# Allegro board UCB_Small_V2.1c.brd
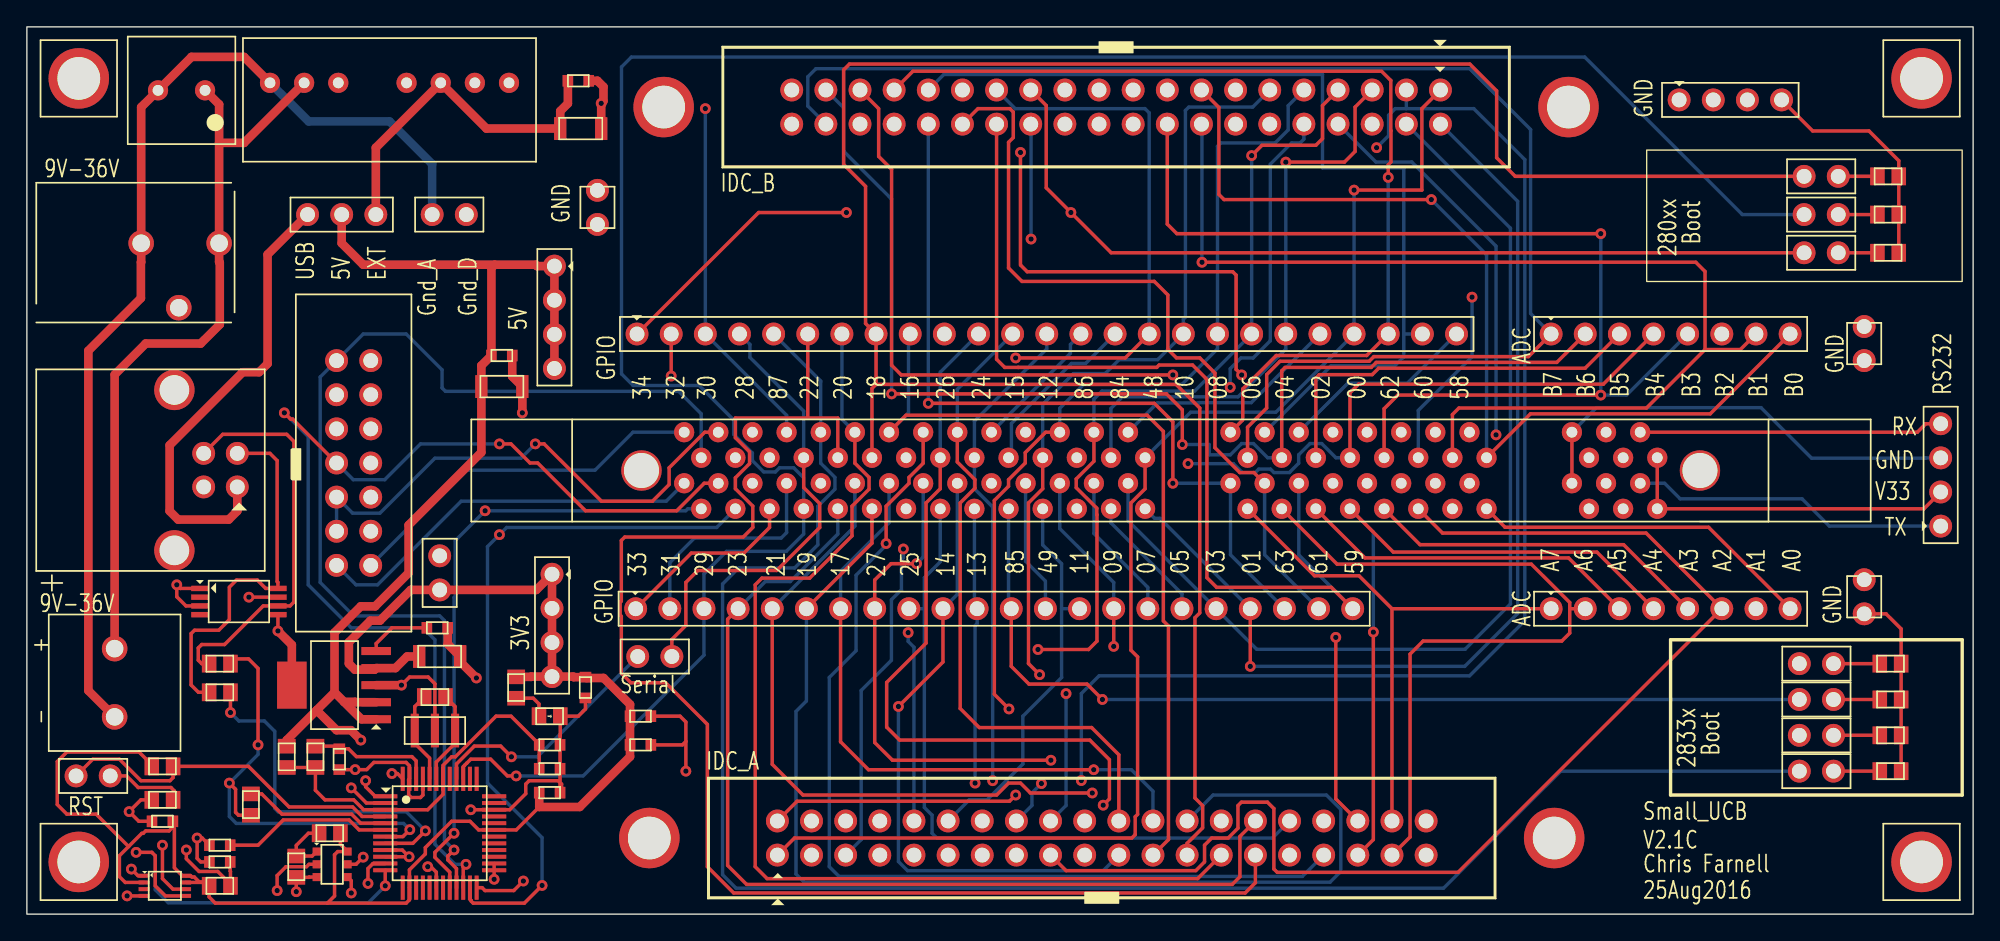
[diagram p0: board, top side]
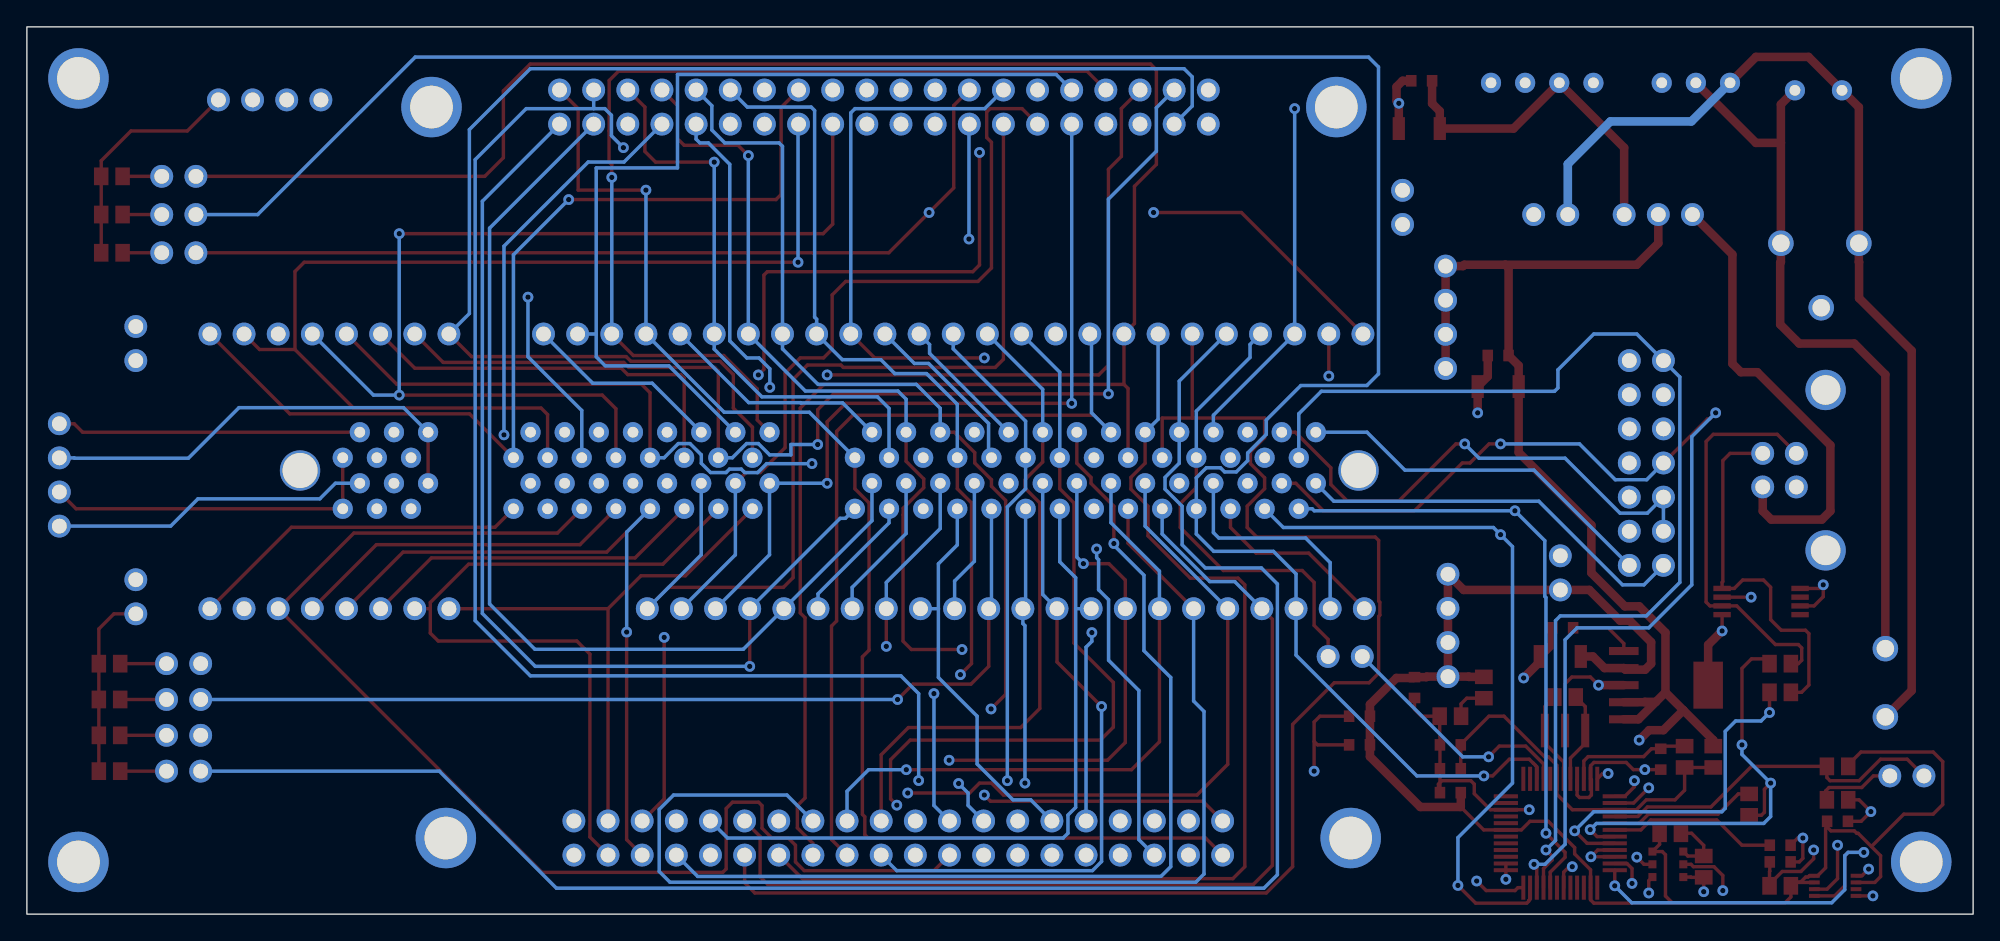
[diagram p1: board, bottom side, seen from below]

Outline 144.78 x 66.04 mm; copper layers: TOP, LAYER2, LAYER3, BOTTOM. Coordinates in mm from the lower left corner of the outline.
Outline path: rectangle 0,0 144.78,66.04

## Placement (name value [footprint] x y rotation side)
C1  100uF  [UVZ1H101MPD]  11.51 61.32 180 top
C2  10uF  [C_1206]  41.2 58.47 0 top
C3  0.1uF  [C_0603]  41.02 62.03 0 top
C4  10uF  [C_1206]  35.33 39.27 0 top
C5  0.1uF  [C_0603]  35.33 41.58 0 top
C6  10uF  [C_1206]  30.71 19.18 0 top
C7  0.1uF  [C_0603]  41.55 16.87 270 top
C8  0.1uF  [C_0603]  30.53 21.31 0 top
C9  0.1uF  [C_0603]  14.35 5.13 0 top
C10  0.1uF  [C_0603]  23.24 11.53 90 top
C11  1uF  [C_0603]  38.89 12.6 0 top
C12  1uF  [C_0603]  38.89 10.82 0 top
C13  0.1uF  [C_0603]  38.89 9.04 0 top
C14  0.1uF  [C_0603]  45.64 14.73 0 top
C15  0.1uF  [C_0603]  45.64 12.6 0 top
C16  0.1uF  [C_0603]  10.08 6.91 180 top
C17  0.1uF  [C_0603]  14.35 3.89 180 top
D1  LED-G  [LED_0805-GREEN]  38.89 14.73 180 top
J1  F28335_DIMM  [5390213-1]  124.46 33.02 180 top
J2  AWHW 14G-0202-T  [14-IDC-M]  24.31 33.58 0 top
J3  Header-4  [H_1X4]  142.37 32.69 180 top
J4  Header_1x22  [H_1X22]  71.96 22.73 90 top
J5  Header_1x25  [H_1X25]  75.87 43.18 90 top
J6  Header_1x8  [H_1X8]  122.28 22.73 90 top
J7  Header_1x8  [H_1X8]  122.28 43.18 90 top
J8  PJ-102BH  [DC-PWR_JACK]  7.95 49.94 90 top
J9  -  [1715721]  6.53 17.22 0 top
J10  670687041  [USB-B_TH]  9.19 33.05 270 top
J11  Header-4  [H_1X4]  39.07 21.49 0 top
J12  Header-4  [H_1X4]  39.24 44.42 0 top
J13  Header-4  [H_1X4]  126.72 60.6 90 top
J14  AWHW 40G-0202-T  [40-IDC-M_MNT]  79.96 5.66 90 top
J15  AWHW 40G-0202-T  [40-IDC-M_MNT]  81.03 60.07 270 top
J16  Header-2  [H_1X2]  136.68 23.62 0 top
J17  Header-2  [H_1X2]  136.68 42.47 0 top
J18  Header-2  [H_1X2]  42.44 52.6 0 top
JP1  -  [J_1X3]  23.42 52.07 90 top
JP2  -  [J_1X2]  31.42 52.07 270 top
JP3  -  [J_1X2]  30.71 25.4 180 top
JP4  -  [J_1X2]  46.71 19.18 90 top
JP5  -  [J_1X2]  4.93 10.29 270 top
JP6  -  [J_1X2]  133.12 10.64 90 top
JP7  -  [J_1X2]  133.12 13.31 90 top
JP8  -  [J_1X2]  133.12 15.98 90 top
JP9  -  [J_1X2]  133.12 18.64 90 top
JP10  -  [J_1X2]  133.48 49.23 90 top
JP11  -  [J_1X2]  133.48 52.07 90 top
JP12  -  [J_1X2]  133.48 54.91 90 top
L1  22uH  [L_0805]  19.33 11.71 270 top
MECH1  Mech_Hole  [4-40_SCREW]  140.94 3.89 0 top
MECH2  Mech_Hole  [4-40_SCREW]  3.86 3.89 0 top
MECH3  Mech_Hole  [4-40_SCREW]  3.86 62.2 0 top
MECH4  Mech_Hole  [4-40_SCREW]  140.94 62.2 0 top
PM1  EC4SAW-24S05N  [SIP-8]  26.97 60.6 90 top
R1  470  [R_0805]  21.46 11.71 90 top
R2  27  [R_0805]  14.35 16.51 0 top
R3  27  [R_0805]  14.35 18.64 0 top
R4  2.2k  [R_0805]  16.66 8.15 90 top
R5  1Meg  [R_0805]  30.35 16.15 180 top
R6  470  [R_0805]  36.4 16.87 270 top
R7  2.2k  [R_0805]  20.04 3.53 270 top
R8  10k  [R_0805]  22.53 6.02 0 top
R9  1k  [R_0805]  14.35 2.11 0 top
R10  47k  [R_0805]  10.08 11 0 top
R11  1k  [R_0805]  10.08 8.51 180 top
R12  2.7k  [R_0805]  138.63 10.64 0 top
R13  2.7k  [R_0805]  138.63 13.31 0 top
R14  2.7k  [R_0805]  138.63 15.98 0 top
R15  2.7k  [R_0805]  138.63 18.64 0 top
R16  2.7k  [R_0805]  138.46 49.23 0 top
R17  2.7k  [R_0805]  138.46 52.07 0 top
R18  2.7k  [R_0805]  138.46 54.91 0 top
TVS1  SN75240PWR  [8-TSSOP]  15.77 23.27 0 top
U1  FT2232D  [LQFP-48]  30.71 6.02 0 top
U2  TPS79533  [SOT-223-6]  22.89 17.04 0 top
U4  SN74LVC2G74  [8-VSSOP]  10.26 2.11 0 top
U5  6 MHz  [CSTCR]  30.35 13.67 90 top
U6  93LC46BT-I/OT  [SOT-23-6]  22.71 3.71 0 top

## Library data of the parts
C1 = CAP P
C2-C17 = CAP NP
D1 = LED
J1 = F28335_DIMM
J2 = Header_2x7
J3 J11-J13 = HEADER 4
J4 = Header_1x22
J5 = Header_1x25
J6 J7 = Header_1x8
J8 = DC-Jack_3
J9 = Connector-2
J10 = USB-B
J14 J15 = Header_2x20
J16-J18 = HEADER 2
JP1 = JP3
JP2-JP12 = JP2
L1 = Ind
MECH1-MECH4 = Mech_Hole
PM1 = EC4SA
R1-R18 = R-Standard
TVS1 = SN75240
U1 = FT2232D
U2 = TPS795
U4 = SN74LVC2G74
U5 = CSTCR_G
U6 = 93LC46BT

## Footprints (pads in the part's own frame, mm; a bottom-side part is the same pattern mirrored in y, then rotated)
4-40_SCREW
  round 4.5 hole 3.175: 1(0,0)
8-TSSOP
  rect 1.3x0.4 smd: 1(-2.9,0.975) 2(-2.9,0.325) 3(-2.9,-0.325) 4(-2.9,-0.975) 5(2.9,-0.975) 6(2.9,-0.325) 7(2.9,0.325) 8(2.9,0.975)
8-VSSOP
  rect 0.8x0.3 smd: 1(-1.55,0.75) 2(-1.55,0.25) 3(-1.55,-0.25) 4(-1.55,-0.75) 5(1.55,-0.75) 6(1.55,-0.25) 7(1.55,0.25) 8(1.55,0.75)
14-IDC-M
  round 1.7 hole 1.1: 1(-1.27,7.62) 2(1.27,7.62) 3(-1.27,5.08) 4(1.27,5.08) 5(-1.27,2.54) 6(1.27,2.54) 7(-1.27,0) 8(1.27,0) 9(-1.27,-2.54) 10(1.27,-2.54) 11(-1.27,-5.08) 12(1.27,-5.08) 13(-1.27,-7.62) 14(1.27,-7.62)
40-IDC-M_MNT
  round 4.5 hole 3.175: (0,33.655) (0,-33.655)
  round 1.7 hole 1.1: 1(-1.27,24.13) 2(1.27,24.13) 3(-1.27,21.59) 4(1.27,21.59) 5(-1.27,19.05) 6(1.27,19.05) 7(-1.27,16.51) 8(1.27,16.51) 9(-1.27,13.97) 10(1.27,13.97) 11(-1.27,11.43) 12(1.27,11.43) 13(-1.27,8.89) 14(1.27,8.89) 15(-1.27,6.35) 16(1.27,6.35) 17(-1.27,3.81) 18(1.27,3.81) 19(-1.27,1.27) 20(1.27,1.27) 21(-1.27,-1.27) 22(1.27,-1.27) 23(-1.27,-3.81) 24(1.27,-3.81) 25(-1.27,-6.35) 26(1.27,-6.35) 27(-1.27,-8.89) 28(1.27,-8.89) 29(-1.27,-11.43) 30(1.27,-11.43) 31(-1.27,-13.97) 32(1.27,-13.97) 33(-1.27,-16.51) 34(1.27,-16.51) 35(-1.27,-19.05) 36(1.27,-19.05) 37(-1.27,-21.59) 38(1.27,-21.59) 39(-1.27,-24.13) 40(1.27,-24.13)
1715721
  round 1.9 hole 1.3: 1(0,2.54) 2(0,-2.54)
5390213-1
  round 3 hole 2.6: (0,0) (78.74,0)
  round 1.5 hole 0.8: 1(3.175,-0.95) 2(4.445,-2.85) 3(5.715,-0.95) 4(6.985,-2.85) 5(8.255,-0.95) 6(9.525,-2.85) 7(15.875,-0.95) 8(17.145,-2.85) 9(18.415,-0.95) 10(19.685,-2.85) 11(20.955,-0.95) 12(22.225,-2.85) 13(23.495,-0.95) 14(24.765,-2.85) 15(26.035,-0.95) 16(27.305,-2.85) 17(28.575,-0.95) 18(29.845,-2.85) 19(31.115,-0.95) 20(32.385,-2.85) 21(33.655,-0.95) 22(34.925,-2.85) 23(41.275,-0.95) 24(42.545,-2.85) 25(43.815,-0.95) 26(45.085,-2.85) 27(46.355,-0.95) 28(47.625,-2.85) 29(48.895,-0.95) 30(50.165,-2.85) 31(51.435,-0.95) 32(52.705,-2.85) 33(53.975,-0.95) 34(55.245,-2.85) 35(56.515,-0.95) 36(57.785,-2.85) 37(59.055,-0.95) 38(60.325,-2.85) 39(61.595,-0.95) 40(62.865,-2.85) 41(64.135,-0.95) 42(65.405,-2.85) 43(66.675,-0.95) 44(67.945,-2.85) 45(69.215,-0.95) 46(70.485,-2.85) 47(71.755,-0.95) 48(73.025,-2.85) 49(74.295,-0.95) 50(75.565,-2.85) 51(3.175,2.85) 52(4.445,0.95) 53(5.715,2.85) 54(6.985,0.95) 55(8.255,2.85) 56(9.525,0.95) 57(15.875,2.85) 58(17.145,0.95) 59(18.415,2.85) 60(19.685,0.95) 61(20.955,2.85) 62(22.225,0.95) 63(23.495,2.85) 64(24.765,0.95) 65(26.035,2.85) 66(27.305,0.95) 67(28.575,2.85) 68(29.845,0.95) 69(31.115,2.85) 70(32.385,0.95) 71(33.655,2.85) 72(34.925,0.95) 73(41.275,2.85) 74(42.545,0.95) 75(43.815,2.85) 76(45.085,0.95) 77(46.355,2.85) 78(47.625,0.95) 79(48.895,2.85) 80(50.165,0.95) 81(51.435,2.85) 82(52.705,0.95) 83(53.975,2.85) 84(55.245,0.95) 85(56.515,2.85) 86(57.785,0.95) 87(59.055,2.85) 88(60.325,0.95) 89(61.595,2.85) 90(62.865,0.95) 91(64.135,2.85) 92(65.405,0.95) 93(66.675,2.85) 94(67.945,0.95) 95(69.215,2.85) 96(70.485,0.95) 97(71.755,2.85) 98(73.025,0.95) 99(74.295,2.85) 100(75.565,0.95)
C_0603
  rect 0.787x0.864 smd: 1(-0.775,0) 2(0.775,0)
C_1206
  rect 0.914x1.702 smd: 1(-1.524,0) 2(1.524,0)
CSTCR
  rect 2.5x0.6 smd: 1(0,1.5) 2(0,0) 3(0,-1.5)
DC-PWR_JACK
  round 1.9 hole 1.3: 1(0,-6.35) 2(0,-0.55) 3(-4.8,-3.35)
H_1X2
  round 1.7 hole 1.1: 1(0,1.27) 2(0,-1.27)
H_1X4
  round 1.7 hole 1.1: 1(0,3.81) 2(0,1.27) 3(0,-1.27) 4(0,-3.81)
H_1X8
  round 1.7 hole 1.1: 1(0,8.89) 2(0,6.35) 3(0,3.81) 4(0,1.27) 5(0,-1.27) 6(0,-3.81) 7(0,-6.35) 8(0,-8.89)
H_1X22
  round 1.7 hole 1.1: 1(0,26.67) 2(0,24.13) 3(0,21.59) 4(0,19.05) 5(0,16.51) 6(0,13.97) 7(0,11.43) 8(0,8.89) 9(0,6.35) 10(0,3.81) 11(0,1.27) 12(0,-1.27) 13(0,-3.81) 14(0,-6.35) 15(0,-8.89) 16(0,-11.43) 17(0,-13.97) 18(0,-16.51) 19(0,-19.05) 20(0,-21.59) 21(0,-24.13) 22(0,-26.67)
H_1X25
  round 1.7 hole 1.1: 1(0,30.48) 2(0,27.94) 3(0,25.4) 4(0,22.86) 5(0,20.32) 6(0,17.78) 7(0,15.24) 8(0,12.7) 9(0,10.16) 10(0,7.62) 11(0,5.08) 12(0,2.54) 13(0,0) 14(0,-2.54) 15(0,-5.08) 16(0,-7.62) 17(0,-10.16) 18(0,-12.7) 19(0,-15.24) 20(0,-17.78) 21(0,-20.32) 22(0,-22.86) 23(0,-25.4) 24(0,-27.94) 25(0,-30.48)
J_1X2
  round 1.7 hole 1.1: 1(0,1.27) 2(0,-1.27)
J_1X3
  round 1.7 hole 1.1: 1(0,2.54) 2(0,0) 3(0,-2.54)
L_0805
  rect 1.08x1.321 smd: 1(-0.794,0) 2(0.794,0)
LED_0805-GREEN
  rect 1.08x1.321 smd: 1(-0.794,0) 2(0.794,0)
LQFP-48
  rect 1.8x0.3 smd: 1(-4.05,2.75) 2(-4.05,2.25) 3(-4.05,1.75) 4(-4.05,1.25) 5(-4.05,0.75) 6(-4.05,0.25) 7(-4.05,-0.25) 8(-4.05,-0.75) 9(-4.05,-1.25) 10(-4.05,-1.75) 11(-4.05,-2.25) 12(-4.05,-2.75) 25(4.05,-2.75) 26(4.05,-2.25) 27(4.05,-1.75) 28(4.05,-1.25) 29(4.05,-0.75) 30(4.05,-0.25) 31(4.05,0.25) 32(4.05,0.75) 33(4.05,1.25) 34(4.05,1.75) 35(4.05,2.25) 36(4.05,2.75)
  rect 0.3x1.8 smd: 13(-2.75,-4.05) 14(-2.25,-4.05) 15(-1.75,-4.05) 16(-1.25,-4.05) 17(-0.75,-4.05) 18(-0.25,-4.05) 19(0.25,-4.05) 20(0.75,-4.05) 21(1.25,-4.05) 22(1.75,-4.05) 23(2.25,-4.05) 24(2.75,-4.05) 37(2.75,4.05) 38(2.25,4.05) 39(1.75,4.05) 40(1.25,4.05) 41(0.75,4.05) 42(0.25,4.05) 43(-0.25,4.05) 44(-0.75,4.05) 45(-1.25,4.05) 46(-1.75,4.05) 47(-2.25,4.05) 48(-2.75,4.05)
R_0805
  rect 1.08x1.321 smd: 1(-0.794,0) 2(0.794,0)
SIP-8
  round 1.5 hole 0.8: 1(1.27,8.89) 2(1.27,6.35) 3(1.27,3.81) 5(1.27,-1.27) 6(1.27,-3.81) 7(1.27,-6.35) 8(1.27,-8.89)
SOT-23-6
  rect 0.6x0.6 smd: 1(-1.15,0.95) 2(-1.15,0) 3(-1.15,-0.95) 4(1.15,-0.95) 5(1.15,0) 6(1.15,0.95)
SOT-223-6
  rect 2.2x0.6 smd: 1(3.1,-2.54) 2(3.1,-1.27) 3(3.1,0) 4(3.1,1.27) 5(3.1,2.54)
  rect 2.2x3.5 smd: 6(-3.175,0)
USB-B_TH
  round 3 hole 2.2: (-5.969,1.778) (5.969,1.778)
  round 1.7 hole 1.1: 1(1.25,6.457) 2(-1.25,6.457) 3(-1.25,3.957) 4(1.25,3.957)
UVZ1H101MPD
  round 1.5 hole 0.8: 1(-1.75,0) 2(1.75,0)

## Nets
3V3: C6.1 C7.1 C13.1 C14.1 C15.1 C16.1 J11.1 J11.2 J11.3 J11.4 JP3.1 R6.1 R8.2 R9.1 R10.1 U1.14(VCCIOA) U1.31(VCCIOB) U2.4(VOUT) U4.2(D) U4.7(PRE) U4.8(VCC) U6.6(VCC)
5V: C4.1 C5.1 J1.77(+5V(4)) J1.82(+5V(3)) J1.87(+5V(2)) J1.92(+5V(1)) J1.96(+5V) J12.1 J12.2 J12.3 J12.4 J14.19 J14.39 J15.19 J15.39 JP1.2 L1.1 U2.1(EN) U2.2(VIN)
5V_EXT: C2.1 C3.1 JP1.3 PM1.6(+VO)
5V_USB: J10.1(5V) JP1.1
GND-ISO: J1.6(GND_ISO) J1.56(GND_ISO(1)) J3.3
GND_SIGNAL: C2.2 C3.2 C4.2 C5.2 C6.2 C7.2 C8.2 C9.1 C10.1 C11.2 C12.2 C13.2 C14.2 C15.2 C16.2 C17.2 D1.1(CATHODE) J1.8(GND_DSP) J1.10(GND_DSP(1)) J1.12(GND_DSP(2)) J1.14(GND_DSP(3)) J1.27(GND_DSP(4)) J1.37(GND_DSP(5)) J1.47(GND_DSP(6)) J1.58(GND_DSP(10)) J1.60(GND_DSP(9)) J1.62(GND_DSP(8)) J1.64(GND_DSP(7)) J2.4 J2.8 J2.10 J2.12 J10.4(GND) J13.1 J13.2 J13.3 J13.4 J14.20 J14.40 J15.20 J15.40 J16.1 J16.2 J17.1 J17.2 J18.1 J18.2 JP2.1 PM1.7(-VO) R11.2 R12.2 R13.2 R14.2 R15.2 R16.2 R17.2 R18.2 TVS1.1(GND1) TVS1.3(GND2) TVS1.5(GND3) TVS1.7(GND4) U1.9(GND4) U1.10(SI/WUA) U1.18(GND3) U1.25(GND2) U1.26(SI/WUB) U1.34(GND1) U1.45(AGND) U1.47(TEST) U2.3(GND) U2.6(GND.) U4.4(GND) U5.2(PIN2) U6.2(GND)
V33-ISO: J1.1(V33D-ISO) J1.51(V33D-ISO(1)) J3.2
ADC-A0: J1.57(ADCIN-A0) J6.8 J14.15
ADC-A1: J1.59(ADCIN-A1) J6.7 J14.16
ADC-A2: J1.61(ADCIN-A2) J6.6 J14.17
ADC-A3: J1.63(ADCIN-A3) J6.5 J14.18
ADC-A4: J1.65(ADCIN-A4) J6.4 J14.35
ADC-A5: J1.67(ADCIN-A5) J6.3 J14.36
ADC-A6: J1.69(ADCIN-A6) J6.2 J14.37
ADC-A7: J1.71(ADCIN-A7) J6.1 J14.38
ADC-B0: J1.7(ADCIN-B0) J7.8 J15.15
ADC-B1: J1.9(ADCIN-B1) J7.7 J15.16
ADC-B2: J1.11(ADCIN-B2) J7.6 J15.17
ADC-B3: J1.13(ADCIN-B3) J7.5 J15.18
ADC-B4: J1.15(ADCIN-B4) J7.4 J15.35
ADC-B5: J1.17(ADCIN-B5) J7.3 J15.36
ADC-B6: J1.19(ADCIN-B6) J7.2 J15.37
ADC-B7: J1.21(ADCIN-B7) J7.1 J15.38
EMU0: J1.100(EMU0) J2.13
EMU1: J1.50(EMU1) J2.14
FTDI_RST: JP5.2 R10.2 U1.4(RESET#)
GPIO-00: J1.23(GPIO-00 / EPWM-1A) J5.22 J14.1 J15.1
GPIO-01: J1.73(GPIO-01 / EPWM-1B / MFSR-B) J4.19 J14.2 J15.2
GPIO-02: J1.24(GPIO-02 / EPWM-2A) J5.21 J14.3 J15.3
GPIO-03: J1.74(GPIO-03 / EPWM-2B / MCLKR-B) J4.18 J14.4 J15.4
GPIO-04: J1.25(GPIO-04 / EPWM-3A) J5.20 J14.5 J15.5
GPIO-05: J1.75(GPIO-05 / EPWM-3B / MFSR-A / EC) J4.17 J14.6 J15.6
GPIO-06: J1.26(GPIO-06 / EPWM-4A / SYNCI / SYN) J5.19 J14.7 J15.7
GPIO-07: J1.76(GPIO-07 / EPWM-4B / MCLKR-A / E) J4.16 J14.8 J15.8
GPIO-08: J1.28(GPIO-08 / EPWM-5A / CANTX-B / A) J5.18 J14.9 J15.9
GPIO-09: J1.78(GPIO-09 / EPWM-5B / SCITX-B / E) J4.15 J14.10 J15.10
GPIO-10: J1.29(GPIO-10 / EPWM-6A / CANRX-B / A) J5.17 J14.11 J15.11
GPIO-11: J1.79(GPIO-11 / EPWM-6B / SCIRX-B / E) J4.14 J14.12 J15.12
GPIO-12: J1.33(GPIO-12 / TZ-1 / CANTX-B / MDX-) J5.13 J14.13
GPIO-13: J1.83(GPIO-13 / TZ-2 / CANRX-B / MDR-) J4.11 J14.14
GPIO-14: J1.84(GPIO-14 / TZ-3 / SCITX-B / MCLK) J4.10 J14.21
GPIO-15: J1.34(GPIO-15 / TZ-4 / SCIRX-B / MFSX) J5.12 J14.22
GPIO-16: J1.38(GPIO-16 / SPISIMO-A / CANTX-B /) J5.9 J14.23
GPIO-17: J1.88(GPIO-17 / SPISOMI-A / CANRX-B /) J4.7 J14.24
GPIO-18: J1.39(GPIO-18 / SPICLK-A / SCITX-B) J5.8 J14.25 JP12.1
GPIO-19: J1.89(GPIO-19 / SPISTE-A / SCIRX-B) J4.6 J14.26
GPIO-20: J1.40(GPIO-20 / EQEPA-1 / MDX-A / CAN) J5.7 J14.27
GPIO-21: J1.90(GPIO-21 / EQEPB-1 / MDR-A / CAN) J4.5 J14.28
GPIO-22: J1.41(GPIO-22 / EQEPS-1 / MCLKX-A / S) J5.6 J14.29
GPIO-23: J1.91(GPIO-23 / EQEPI-1 / MFSX-A / SC) J4.4 J14.30
GPIO-24: J1.35(GPIO-24 / ECAP-1 / EQEPA-2 / MD) J5.11 J14.31
GPIO-25: J1.85(GPIO-25 / ECAP-2 / EQEPB-2 / MD) J4.9 J14.32
GPIO-26: J1.36(GPIO-26 / ECAP-3 / EQEPI-2 / MC) J5.10 J14.33
GPIO-27: J1.86(GPIO-27 / ECAP-4 / EQEPS-2 / MF) J4.8 J14.34
GPIO-30: J1.44(GPIO-30 / CANRX-A) J5.3 J15.21
GPIO-31: J1.94(GPIO-31 / CANTX-A) J4.2 J15.22
GPIO-32: J1.45(GPIO-32 / I2CSDA / SYNCI / ADCS) J5.2 J15.23
GPIO-33: J1.95(GPIO-33 / I2CSCL / SYNCO / ADCS) J4.1 J15.24
GPIO-34: J1.46(GPIO-34 / ECAP1 / XREADY (EMIF)) J5.1 J15.25 JP10.1
GPIO-48: J1.30(GPIO-48 / ECAP5 / XD31 (EMIF)) J5.16 J15.27
GPIO-49: J1.80(GPIO-49 / ECAP6 / XD30 (EMIF)) J4.13 J15.26
GPIO-58: J1.18(GPIO-58 / MCLKR-A / XD21 (EMIF)) J5.25 J15.29
GPIO-59: J1.68(GPIO-59 / MFSR-A / XD20 (EMIF)) J4.22 J15.28
GPIO-60: J1.20(GPIO-60 / MCLKR-B / XD19 (EMIF)) J5.24 J15.31
GPIO-61: J1.70(GPIO-61 / MFSR-B / XD18 (EMIF)) J4.21 J15.30
GPIO-62: J1.22(GPIO-62 / SCIRX-C / XD17 (EMIF)) J5.23 J15.33
GPIO-63: J1.72(GPIO-63 / SCITX-C / XD16 (EMIF)) J4.20 J15.32
GPIO-84: J1.31(GPIO-84) J5.15 JP9.1
GPIO-85: J1.81(GPIO-85) J4.12 JP8.1
GPIO-86: J1.32(GPIO-86) J5.14 JP7.1
GPIO-87: J1.42(GPIO-87) J5.5 JP6.1
RX-ISO: J1.2(ISO-RX-RS232) J3.4
RX_SLAVE: J1.43(GPIO-28 / SCIRX-A / RESV / TZ5) J5.4 JP4.2
TCK: J1.48(TCK) J2.9 J2.11 U1.24(ADBUS0)
TDI: J1.97(TDI) J2.3 U1.23(ADBUS1)
TDO: J1.98(TDO) J2.7 U1.22(ADBUS2)
TMS: J1.49(TMS) J2.1 U1.21(ADBUS3)
TRSTN: J1.99(TRSTN) J2.2 U1.20(ADBUS4)
TX-ISO: J1.52(ISO-TX-RS232) J3.1
TX_SLAVE: J1.93(GPIO-29 / SCITX-A / RESV / TZ6) J4.3 JP11.1 U1.39(BDBUS1)
USB_D+: R3.2 R4.1 U1.7(USBDP)
USB_D-: R2.2 U1.8(USBDM)
N12195: C1.1 J8.1 J9.1(P1) PM1.2(+VIN)
N12272: C1.2 J8.2 J9.2(P2) JP2.2 PM1.1(-VIN)
N18531: C8.1 U2.5(NR/FB)
N22439: J10.2(D-) R2.1 TVS1.8(A)
N22457: J10.3(D+) R3.1 TVS1.6(B)
N23366: R4.2 U1.5(RSTOUT#)
N23404: R5.2 U1.44(XTOUT) U5.1(PIN1)
N23422: R5.1 U1.43(XTIN) U5.3(PIN3)
N24717: C9.2 U1.6(3V3OUT)
N25180: D1.2(ANODE) R6.2
N25279: C11.1 C12.1 L1.2 R1.1 U1.3(VCC1) U1.42(VCC2)
N25286: C10.2 R1.2 U1.46(AVCC)
N28281: J2.5 JP3.2
N29672: U1.11(ACBUS3) U4.1(CLK)
N29684: U1.12(ACBUS2) U4.5(Q)
N29790: JP4.1 U1.40(BDBUS0)
N34054: R7.1 R8.1 U6.1(DO)
N34072: R7.2 U1.2(EEDATA) U6.3(DI)
N34220: U1.1(EESK) U6.4(CLK)
N34232: U1.48(EECS) U6.5(CS)
N41056: C17.1 R9.2 U4.6(NOT CLR)
N43288: JP5.1 R11.1
N46408: JP10.2 R16.1
N46412: JP11.2 R17.1
N46416: JP12.2 R18.1
N46420: JP6.2 R12.1
N46424: JP7.2 R13.1
N46428: JP8.2 R14.1
N46432: JP9.2 R15.1

Pads without a net: J1 3 4 5 16 53 54 55 66; J2 6; J8 3; J15 13 14 34; MECH1 1; MECH2 1; MECH3 1; MECH4 1; PM1 3 5 8; TVS1 2 4; U1 13 15 16 17 19 27 28 29 30 32 33 35 36 37 38 41; U4 3

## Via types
v1: diameter 0.8, hole 0.4, TOP to BOTTOM, 96 vias

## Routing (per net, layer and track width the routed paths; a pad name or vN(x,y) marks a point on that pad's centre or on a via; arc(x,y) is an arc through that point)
3V3: length 126.1
  TOP w0.254: 7.56,5.03 6.88,4.35 6.88,2.79 7.32,2.36 U4.2 ; 7.56,5.03 8.55,6.01 8.66,6.01 8.84,6.2 10.58,6.2 10.86,6.48 ; 7.56,5.03 5.15,7.44 2.97,7.44 2.26,8.15 2.26,11.35 2.97,12.06 8.34,12.06 9.29,11.12 R10.1 ; 13.22,2.4 13.5,2.11 R9.1 13.56,1.28 14.02,0.82 22.35,0.82 ; 13.22,2.4 13.18,2.36 U4.7 ; 13.22,2.4 12.82,2.4 12.45,2.76 12.27,2.76 12.18,2.86 U4.8 11.56,2.86 10.97,3.45 10.97,6.36 10.86,6.48 ; 10.86,6.48 C16.1 ; 38.11,7.98 36.41,6.27 U1.31 33.6,6.27 32.97,6.91 31.6,6.91 29.64,4.95 29.64,4.48 28.46,3.3 U1.14 28.46,1.06 28.21,0.82 22.35,0.82 ; 22.35,0.82 22.89,1.35 22.89,4.42 23.12,4.66 U6.6 23.32,5.19 R8.2
  TOP w0.635: J11.4 J11.3 J11.2 J11.1 37.9,24.13 JP3.1 28.55,24.13 26.26,21.84 25.55,21.84 23.95,20.24 23.95,18.64 24.4,18.19 25.87,18.19 U2.4 27.42,18.31 28.28,19.18 C6.1 ; J11.4 40.64,17.68 40.68,17.64 C7.1 41.62,17.58 42.9,17.58 44.87,15.61 C14.1 C15.1 44.87,11.72 41.12,7.98 38.11,7.98 C13.1 ; J11.4 37.52,17.68 37.5,17.66 R6.1
5V: length 291.8
  TOP w0.635: 23.6,15.8 22.89,16.51 ; 23.6,15.8 24.42,15.8 24.44,15.77 U2.2 ; 23.6,15.8 24.89,14.5 U2.1 ; 22.89,16.51 22.89,20.95 24.84,22.91 25.91,22.91 28.4,25.4 28.4,28.96 33.81,34.37 C4.1 33.81,40.83 C5.1 34.56,48.09 34.8,48.34 ; 22.89,16.51 21.55,15.18 ; JP1.2 23.42,49.94 25.02,48.34 34.8,48.34 ; 34.8,48.34 37.85,48.34 37.95,48.23 J12.1 J12.2 J12.3 J12.4 ; 21.55,15.18 19.33,12.95 L1.1 ; 21.55,15.18 23.04,13.69 24.1,13.69 v1(24.84,12.95)
  LAYER3 w0.635: 56.85,63.98 79.65,63.98 J15.19 ; 56.85,63.98 56.9,63.93 J15.39 ; 56.85,63.98 45.09,63.98 39.24,58.14 J12.1 ; J1.92 59.06,28.7 59.16,28.6 ; v1(24.84,12.95) 43.51,12.95 55.07,1.4 78.71,1.4 ; 78.71,1.4 78.69,1.42 J14.19 ; 78.71,1.4 103.61,1.4 104.09,1.88 J14.39 ; 65.38,28.6 65.41,28.63 J1.87 ; 65.38,28.6 71.78,28.6 ; 65.38,28.6 59.16,28.6 ; 71.78,28.6 71.75,28.63 J1.82 ; 71.78,28.6 76.41,28.6 77.98,30.17 J1.77 ; 59.16,28.6 54,28.6 ; J1.96 53.98,28.63 54,28.6 ; 54,28.6 39.88,28.6 39.24,29.24 J12.4
5V_EXT: length 25.9
  TOP w0.635: C3.1 40.25,60.34 39.67,59.77 C2.1 34.19,58.47 PM1.6 25.96,57.05 JP1.3
5V_USB: length 34.4
  TOP w0.635: JP1.1 17.91,49.1 17.91,40.97 17.27,40.34 16.05,40.34 10.62,34.9 10.62,30 11.25,29.37 15.02,29.37 15.65,30 J10.1
GND-ISO: length 33.6
  TOP w0.254: J1.56 J1.6
  BOTTOM w0.254: J1.6 116.76,37.7 129,37.7 132.77,33.93 141.24,33.93 141.26,33.96 J3.3
GND_SIGNAL: length 122.8
  TOP w0.254: TVS1.7 v1(16.52,23.59) ; U1.9 27.93,4.77 v1(28.43,4.27) U1.10 ; U5.2 30.35,17.15 29.85,17.65 28.47,17.65 v1(27.86,17.04) ; C14.2 48.59,14.73 49.02,14.3 49.02,12.85 ; C9.1 13.04,5.66 v1(12.67,5.66) 12.67,4.15 12.93,3.89 C17.2 ; J13.4 132.84,58.29 137.03,58.29 139.25,56.08 R18.2 R17.2 R16.2 ; R11.2 8.48,8.51 v1(7.61,7.63) 8.33,6.91 C16.2 ; J16.2 138.3,22.35 139.43,21.23 R15.2 R14.2 R13.2 R12.2 ; v1(29.82,3.53) 30.05,3.53 30.46,3.12 U1.18 ; U6.2 20.98,3.71 20.81,3.53 19.27,3.53 18.62,2.87 v1(18.62,1.75) ; 49.02,12.85 v1(49.02,10.64) ; 49.02,12.85 48.77,12.6 C15.2 ; v1(34.76,2.59) U1.25 U1.26 ; C10.1 v1(24.42,10.76) 25.28,10.76 25.81,11.29 28.2,11.29 28.46,11.04 U1.47 28.4,10.01 28.4,8.86 28.58,8.68 29.28,8.68 29.46,8.86 U1.45 ; TVS1.1 11.42,24.24 v1(11.15,24.51) 11.15,23.62 11.83,22.94 TVS1.3 ; U4.4 v1(7.46,1.36) ; C7.2 41.55,15.27 41.02,14.73 D1.1 39.68,13.3 39.66,13.28 C11.2 C12.2 C13.2 39.78,9.16 39.78,9.68 39.52,9.93 37.36,9.93 37.11,9.68 37.11,8.97 35.91,7.77 U1.34 v1(33.02,7.77) ; TVS1.5 v1(18.67,21.08)
  TOP w0.635: C8.2 31.31,20.1 C6.2 32.23,18.78 v1(33.44,17.58) ; C3.2 42.44,62.03 42.89,61.58 42.89,60.52 v1(42.72,60.35) C2.2 ; v1(36.86,37.31) C4.2 36.11,40.02 C5.2 ; v1(18.67,21.08) 19.71,20.04 U2.6 ; U2.3 v1(27.86,17.04)
V33-ISO: length 25.4
  TOP w0.254: J3.2 141.12,30.17 J1.51 J1.1
ADC-A0: length 85.2
  TOP w0.254: J6.8 125.1,28.79 109.96,28.79 J1.57
  LAYER3 w0.254: J14.15 74.8,5.59 74.8,8.86 74.63,9.04 74.63,12.17 75.06,12.6 107.7,12.6 108.59,13.49 J1.57
ADC-A1: length 82.2
  LAYER3 w0.254: J1.59 107.1,30.17 107.53,30.6 107.53,30.61 108.15,31.22 108.15,31.22 108.2,31.27 109.64,31.27 109.9,31.01 109.9,21.21 110.08,21.03 ; v1(75.47,9.72) 75.47,11.91 75.72,12.16 108.32,12.16 110.08,13.91 110.08,21.03 ; 110.08,21.03 110.33,20.78 126.67,20.78 J6.7
  BOTTOM w0.254: v1(75.47,9.72) 74.76,9.02 74.76,8.09 J14.16
ADC-A2: length 92.8
  TOP w0.254: 103.5,30.17 105.31,28.36 120.46,28.36 J6.6 106.46,3.11 93.01,3.11 92.76,3.36 92.76,7.86 92.29,8.33 90.35,8.33 90.09,8.08 90.09,6.4 89.36,5.66 88.14,5.66 87.6,5.13 87.6,3.89 86.96,3.24 77.3,3.24 J14.17
ADC-A3: length 71.4
  TOP w0.254: J1.63 103.64,27.5 118.78,27.5 J6.5
  LAYER3 w0.254: J1.63 100.97,19.15 80.04,19.15 v1(77.3,16.41)
  BOTTOM w0.254: J14.18 77.3,8.09 v1(77.3,16.41)
ADC-A4: length 52.6
  TOP w0.254: J6.4 116.79,26.95 101.65,26.95 J1.65 ; J14.35 100.16,5.55 v1(100.16,20.99)
  BOTTOM w0.254: v1(100.16,20.99) 100.16,28.43 J1.65
ADC-A5: length 50.2
  TOP w0.254: 95.88,30.17 99.54,26.51 114.68,26.51 J6.3 ; J14.36 97.37,8.57 v1(97.37,20.6)
  LAYER3 w0.254: v1(97.37,20.6) 97.37,28.68 95.88,30.17
ADC-A6: length 55.8
  TOP w0.254: 114.77,22.73 J6.2 ; 114.77,22.73 114.77,20.92 114.18,20.33 103.87,20.33 102.9,19.35 102.9,5.74 J14.37 ; 114.77,22.73 114.77,23.2 111.92,26.05 97.47,26.05 J1.69
ADC-A7: length 41.5
  TOP w0.254: J14.38 101.55,22.73 ; 101.55,22.73 99.1,25.18 95.79,25.18 J1.71 ; 101.55,22.73 J6.1
ADC-B0: length 71.6
  TOP w0.254: J7.8 125.22,37.24 111.85,37.24 J1.7 ; J15.15 88.67,60.05 88.67,53.57 89.06,53.18 v1(104.48,53.18)
  BOTTOM w0.254: v1(104.48,53.18) 108.59,49.08 J1.7
ADC-B1: length 82.1
  TOP w0.254: 124.84,42.03 124.84,47.83 124.15,48.52 v1(87.42,48.52) ; 124.84,42.03 120.48,37.67 106.53,37.67 106.05,37.19 J1.9 ; 124.84,42.03 127.47,42.03 J7.7
  BOTTOM w0.254: v1(87.42,48.52) 87.42,58.76 J15.16
ADC-B2: length 73.6
  LAYER3 w0.254: J15.17 86.41,62.92 106.81,62.92 107.97,61.76 107.97,47.04 107.5,46.58 v1(107.5,45.92) 123.34,45.92 J7.6
  BOTTOM w0.254: 103.5,33.97 103.5,37.49 107.5,41.49 v1(107.5,45.92)
ADC-B3: length 80.5
  TOP w0.254: v1(117.08,50.65) 85.55,50.65 84.84,51.36 J15.18 ; J1.13 100.97,37.62 101.98,38.63 v1(117.08,38.63)
  BOTTOM w0.254: J7.5 119,38.63 v1(117.08,38.63) v1(117.08,50.65)
ADC-B4: length 93.2
  TOP w0.254: J1.15 98.43,38.81 99.06,39.45 117.27,39.45 J7.4 ; v1(85.25,40.13) 65.05,40.13 64.32,40.86 64.32,55.44 63.36,56.4 63.36,59.96 J15.35
  LAYER3 w0.254: v1(86.38,33.53) 85.25,34.66 v1(85.25,40.13)
  BOTTOM w0.254: v1(86.38,33.53) 89.75,33.53 90.42,32.87 91.38,32.87 91.64,33.12 92.51,33.12 92.77,32.87 93.92,32.87 94.61,33.56 94.61,34.19 95.45,35.02 96.32,35.02 97.38,33.97 J1.15
ADC-B5: length 85.8
  TOP w0.254: v1(73.91,56.69) 73.91,48.32 74.41,47.82 89.7,47.82 89.95,47.56 89.95,40.55 v1(90.37,40.13) ; J7.3 115.92,40.63 100.56,40.63 100.08,40.16 96.14,40.16 95.88,39.9 95.88,33.97
  LAYER3 w0.254: v1(73.91,56.69) 64.08,56.69 J15.36 ; 95.88,33.97 95.88,38.63 94.38,40.13 v1(90.37,40.13)
ADC-B6: length 88.5
  TOP w0.254: J1.19 93.35,40.44 93.6,40.69 100,40.69 100.38,41.07 113.81,41.07 J7.2 ; v1(64.32,38.72) 84.77,38.72 85.95,37.54 v1(85.95,34.96)
  BOTTOM w0.254: J1.19 92.3,33.97 91.24,35.02 90.37,35.02 89.53,34.19 87.95,34.19 87.95,34.96 v1(85.95,34.96) ; J15.37 60.76,60.02 60.76,56.79 64.32,53.22 v1(64.32,38.72)
ADC-B7: length 105
  TOP w0.254: J7.1 111.7,41.5 100.2,41.5 99.85,41.15 93.22,41.15 92.23,40.16 92.23,37.67 90.81,36.25 J1.21
  BOTTOM w0.254: J7.1 111.86,44.7 111.86,58.39 107.33,62.93 58.7,62.93 58.09,62.32 58.09,60.15 J15.38
EMU0: length 29.6
  BOTTOM w0.254: J1.100 47.56,30.73 32.31,30.73 26.09,24.51 24.49,24.51 J2.13
EMU1: length 27.4
  BOTTOM w0.254: J2.14 32.66,33.05 42.27,33.05 45.09,35.87 J1.50
FTDI_RST: length 26.7
  TOP w0.254: JP5.2 4.9,11.53 6.88,11.53 8.48,9.93 10.64,9.93 10.88,10.17 R10.2 16.48,11 19.51,7.98 24.23,7.98 24.94,7.27 U1.4
GPIO-00: length 99.2
  TOP w0.254: v1(98.73,53.89) 103.77,53.89 103.77,59.96 J15.1 ; J14.1 57.1,5.66 82.19,5.66 82.45,5.92 82.45,7.25 82.63,7.42 82.63,19.15 82.13,19.64 82.13,30.61 83.19,31.66 83.19,33.97
  BOTTOM w0.254: v1(98.73,53.89) J5.22 92.91,37.36 86.57,37.36 83.19,33.97
GPIO-01: length 117.7
  TOP w0.254: v1(73.56,8.86) 73.1,8.4 57.3,8.4 J14.2 ; v1(91.01,18.44) J4.19
  LAYER3 w0.254: v1(73.56,8.86) 73.56,12.65 74.36,13.45 86.02,13.45 v1(91.01,18.44)
  BOTTOM w0.254: J15.2 110.9,53.06 110.9,22.38 106.96,18.44 v1(91.01,18.44) ; 83.19,30.17 83.9,29.46 84.28,29.46 J4.19
GPIO-02: length 151.6
  LAYER3 w0.254: J14.3 59.52,3.24 77.3,3.24 77.3,8.81 v1(78.44,9.94) ; v1(100.41,57.05) 100.41,47.4 J5.21
  BOTTOM w0.254: 102.62,59.96 107.63,59.96 111.43,56.16 111.43,21.84 107.32,17.74 79.76,17.74 78.44,16.41 v1(78.44,9.94) ; 102.62,59.96 101.79,59.96 101.3,59.46 101.3,57.94 v1(100.41,57.05) ; 102.62,59.96 J15.3 ; J1.24 84.09,38.05 87.2,38.05 87.22,38.07 91.08,38.07 J5.21
GPIO-03: length 122.9
  LAYER3 w0.254: J14.4 59.14,7.71 59.14,23.96 59.97,24.79 75.88,24.79 75.9,24.82 81.33,24.82 81.92,25.4 J1.74
  BOTTOM w0.254: J1.74 81.92,29.29 J4.18 91.49,19.71 106.98,19.71 110.36,23.09 110.36,51.05 J15.4
GPIO-04: length 89.1
  TOP w0.254: v1(93.65,55.97) 98.01,55.97 98.81,56.77 98.81,60.07 J15.5
  LAYER3 w0.254: J1.25 79.6,33.97 78.06,32.44 78.06,31.7 79.16,30.61 79.16,29.51 76.82,27.18 v1(65.2,27.18)
  BOTTOM w0.254: v1(65.2,27.18) 65.2,26.52 65.06,26.38 65.06,24.15 64.31,23.4 64.31,18.9 62.06,16.65 62.06,5.55 J14.5 ; J1.25 80.65,37.64 81.51,38.5 90.1,38.5 93.65,42.05 J5.20 v1(93.65,55.97)
GPIO-05: length 109.7
  LAYER3 w0.254: J15.6 87.3,46.02 77.55,46.02 77.11,45.59 77.11,40.16 80.85,36.42 80.85,35.26 81.11,35 81.29,35 81.92,34.38 81.92,33.58 80.65,32.31 J1.75 75.7,25.22 56.07,25.22 54.18,23.33 54.18,6.73 55.25,5.66 59.64,5.66 J14.6
  BOTTOM w0.254: J4.17 85.93,23.84 80.65,29.12 J1.75
GPIO-06: length 89
  TOP w0.254: J15.7 96.38,60.19 96.38,57.72 95.88,57.23 91.88,57.23 v1(91.11,56.46) ; J1.26 79.38,33.71 78.06,32.39 78.06,31.74 79.59,30.21 79.59,29.73 79.6,29.72 79.6,20.32 78.98,19.7 v1(75.21,19.7)
  LAYER3 w0.254: v1(75.21,19.7) 63.05,19.7 62.29,18.94 62.29,5.55 J14.7
  BOTTOM w0.254: J1.26 79.38,38.33 79.98,38.94 86.87,38.94 J5.19 v1(91.11,56.46)
GPIO-07: length 112.5
  LAYER3 w0.254: v1(109.29,35.67) 104.09,40.87 84.84,40.87 84.4,40.44 84.4,31.92 84.58,31.74 84.58,23.93 J4.16 81.29,20.63 77.15,20.63 J14.8
  BOTTOM w0.254: J15.8 100.36,55.98 103.02,55.98 109.29,49.72 v1(109.29,35.67) ; J4.16 83.39,24.32 79.38,28.33 J1.76
GPIO-08: length 77.1
  TOP w0.254: v1(73.06,15.27) 71.97,16.36 71.97,30.79 73.03,31.85 73.03,32.33 74.27,33.58 74.27,34.35 75.79,35.87 J1.28
  LAYER3 w0.254: v1(73.06,15.27) 73.06,14.35 67.14,8.44 67.14,5.55 J14.9
  BOTTOM w0.254: J15.9 93.83,60.17 93.83,58.37 92.86,57.4 88.82,57.4 88.57,57.15 J5.18 88.57,42.08 85.92,39.43 78.61,39.43 76.84,37.65 J1.28
GPIO-09: length 92.4
  TOP w0.254: v1(80.85,19.93) J4.15
  LAYER3 w0.254: v1(65.56,20.95) 66.21,20.95 66.32,21.07 79.18,21.07 J4.15 ; v1(89.52,39.21) 87.31,37.01 87.31,21.73 85.51,19.93 v1(80.85,19.93)
  BOTTOM w0.254: J15.10 95,57.68 94.72,57.4 94.08,57.4 92.49,55.82 92.49,42.67 91.22,41.4 90.32,41.4 89.52,40.59 v1(89.52,39.21) ; v1(65.56,20.95) 65.56,20.3 65.99,19.87 J14.10 ; J1.78 76.84,28.7 80.85,24.69 J4.15
GPIO-10: length 73.4
  TOP w0.254: 75.56,33.97 75.56,31.66 74.51,30.61 74.51,18.65 v1(75.34,17.82)
  LAYER3 w0.254: J14.11 69.68,5.55 69.68,10.04 73.76,14.12 73.76,16.25 v1(75.34,17.82)
  BOTTOM w0.254: 75.56,33.97 75.56,37.95 77.85,40.23 80.21,40.23 81.25,41.27 84.12,41.27 J5.17 86.03,44.28 86.18,44.44 86.18,59.82 86.44,60.07 91.19,60.07 J15.11
GPIO-11: length 70.8
  LAYER3 w0.254: J15.12 82.17,48.51 75.23,48.51 74.71,47.99 74.71,40.98 75.35,40.35 75.35,35.88 75.78,35.45 75.78,35.43 76.4,34.82 76.41,34.82 76.76,34.47 76.76,33.58 75.56,32.38 75.56,30.17
  BOTTOM w0.254: 76.97,22.73 76.97,17.61 74.09,14.73 74.09,11.18 71.43,8.51 70.1,8.51 J14.12 ; 76.97,22.73 76.97,26.08 75.56,27.48 75.56,30.17 ; 76.97,22.73 J4.14
GPIO-12: length 42.3
  LAYER3 w0.254: J14.13 72.31,5.63 72.31,9.47 v1(71.84,9.93)
  BOTTOM w0.254: v1(71.84,9.93) 71.84,30.3 70.49,31.66 J1.33 70.49,36.69 75.87,42.08 J5.13
GPIO-13: length 23.6
  LAYER3 w0.254: v1(70.54,9.75) 70.54,9.1 70.94,8.69 70.94,7.06 J14.14
  BOTTOM w0.254: v1(70.54,9.75) 70.54,21.48 70.69,21.63 J4.11 70.49,22.94 J1.83
GPIO-14: length 47.1
  TOP w0.254: J4.10 68.15,18.77 v1(64.83,15.46)
  BOTTOM w0.254: J14.21 80.07,3.24 65.51,3.24 64.83,3.92 v1(64.83,15.46) ; J4.10 69.22,23.8 J1.84
GPIO-15: length 48.7
  TOP w0.254: J14.22 81.23,11.86 79.2,13.89 70.85,13.89 69.43,15.3 69.43,30.61 70.53,31.7 70.53,32.34 69.22,33.66 J1.34
  BOTTOM w0.254: J1.34 69.22,39.07 J5.12
GPIO-16: length 61.6
  TOP w0.254: J1.38 65.4,37.13 83.34,37.13 84.54,35.93 84.54,21.82 84.92,21.44 84.92,5.55 J14.23
  BOTTOM w0.254: J1.38 65.58,37.32 65.58,43.05 J5.9
GPIO-17: length 47.7
  TOP w0.254: J4.7 60.53,12.83 62.61,10.75 v1(79.36,10.75)
  BOTTOM w0.254: v1(79.36,10.75) 82.16,10.75 83.77,9.14 J14.24 ; J1.88 64.13,29.13 60.53,25.53 J4.7
GPIO-18: length 166.9
  TOP w0.254: J14.25 86.31,5.27 87.46,6.42 87.46,8.07 86.89,8.64 86.89,22.06 87.25,22.42 87.25,37.67 85.49,39.43 63.17,39.43 ; 63.17,39.43 62.87,39.12 62.87,33.97 ; 63.17,39.43 J5.8 62.39,43.96 62.39,54.17 60.76,55.8 60.76,62.84 61.19,63.27 107.34,63.27 109.33,61.28 109.33,56.3 110.72,54.91 JP12.1
GPIO-19: length 87.9
  TOP w0.254: 62.87,30.17 62.87,27.61 J4.6
  BOTTOM w0.254: J4.6 57.99,15.86 57.21,15.09 57.21,2.98 57.82,2.38 96.94,2.38 97.74,3.18 97.74,7.8 96.67,8.86 88.24,8.86 J14.26
GPIO-20: length 81.8
  TOP w0.254: J1.40 61.6,33.56 62.65,32.51 62.65,31.63 61.38,30.36 61.38,28.16 58.23,25.01 54.68,25.01 54.18,24.51 54.18,3.53 55.07,2.64 87.1,2.64 J14.27
  BOTTOM w0.254: J5.7 60.63,36.84 J1.40
GPIO-21: length 59.3
  TOP w0.254: J4.5 55.45,11.15 57.73,8.86 72.14,8.86 73.02,9.75 73.91,9.75 74.65,9.02 v1(79.25,9.02)
  LAYER3 w0.254: J14.28 86.77,9.02 v1(79.25,9.02)
  BOTTOM w0.254: J1.90 61.6,28.88 J4.5
GPIO-22: length 109
  TOP w0.254: 60.32,33.97 60.32,36.92 58.09,36.92 ; 58.09,36.92 J5.6 ; 58.09,36.92 52.71,36.92 52.71,35.46 53.76,34.41 53.76,33.53 52.71,32.48 52.71,31.66 54,30.37 54,28.78 53.29,28.07 44.48,28.07 44.22,27.81 44.22,23.3 44.13,23.21 44.13,22.25 44.22,22.17 44.22,17.93 44.93,17.22 47.52,17.22 50.62,14.12 50.62,3.53 52.58,1.57 90.63,1.57 91.39,2.34 J14.29
GPIO-23: length 74.6
  TOP w0.254: J4.4 52.13,21.95 52.13,3.63 53.54,2.21 89.66,2.21 90.23,2.78 90.23,5.78 J14.30
  BOTTOM w0.254: J4.4 54.93,24.75 56.78,24.75 60.32,28.29 60.32,30.17
GPIO-24: length 70
  TOP w0.254: 67.94,33.97 67.94,31.66 66.89,30.61 66.89,20.18 63.96,17.24 63.96,13.92 64.92,12.95 79.07,12.95 80.53,11.5 80.53,8.57 v1(80.07,8.11)
  LAYER3 w0.254: v1(80.07,8.11) 80.07,7.46 79.96,7.35 79.96,6.13 80.43,5.66 92.66,5.66 J14.31
  BOTTOM w0.254: 67.94,33.97 67.94,40.34 J5.11
GPIO-25: length 53.3
  BOTTOM w0.254: 66.76,22.73 66.76,7.94 67.34,7.37 67.34,6.02 67.69,5.66 92.66,5.66 J14.32 ; 66.76,22.73 J4.9 ; 66.76,22.73 66.76,25.04 67.94,26.23 67.94,30.17
GPIO-26: length 80.9
  TOP w0.254: v1(63.92,27.58) 63.92,30.36 65.62,32.06 65.62,32.51 66.68,33.56 J1.36
  LAYER3 w0.254: J5.10 68.12,43.05 68.12,37.32 J1.36
  BOTTOM w0.254: v1(63.92,27.58) 63.92,27.46 61.68,25.23 61.68,19.61 59.69,17.62 59.69,3.53 60.41,2.81 94.88,2.81 J14.33
GPIO-27: length 57.7
  TOP w0.254: v1(76.17,11.45) 64.39,11.45 63.07,12.78 J4.8 63.07,24.87 64.29,26.09 v1(66.19,26.09)
  LAYER3 w0.254: v1(76.17,11.45) 91.95,11.45 J14.34
  BOTTOM w0.254: J1.86 66.68,26.57 v1(66.19,26.09)
GPIO-30: length 59.1
  LAYER3 w0.254: J15.21 78.11,62.99 58.7,62.99 58.05,62.34 58.05,60.21 57.8,59.96 v1(50.47,59.96)
  BOTTOM w0.254: v1(50.47,59.96) J5.3 56.52,37.13 J1.44
GPIO-31: length 63.7
  LAYER3 w0.254: J15.22 79.76,56.85 76.94,54.03 61.11,54.03 59.51,52.43 59.51,43.7 59.47,43.66 59.47,42.7 59.51,42.66 59.51,37.85 60.4,36.96 60.4,35.71 59.06,34.37 59.06,33.56 57.56,32.07 J1.94
  BOTTOM w0.254: J1.94 56.52,28.4 56.11,27.99 49.66,27.99 47.83,26.16 J4.2
GPIO-32: length 66.2
  TOP w0.254: v1(47.93,40.05) J5.2
  LAYER3 w0.254: v1(47.93,40.05) 47.93,39.4 47.6,39.07 47.6,35.18 48.18,34.59 49.15,34.59 49.58,35.02 50.78,35.02 51.44,34.36 51.44,33.65 52.22,32.87 53.11,32.87 54.21,33.97 55.25,33.97 ; J15.23 76,62.56 61.01,62.56 60.76,62.31 60.76,57.58 60.22,57.05 48.67,57.05 47.93,56.31 J5.2
GPIO-33: length 62.3
  TOP w0.254: 55.25,30.17 55.25,28.78 53.34,26.87 49.43,26.87 J4.1
  LAYER3 w0.254: 55.25,30.17 55.25,32.33 56.49,33.58 56.49,34.29 55.46,35.32 55.46,36.67 56.93,38.15 56.93,53.4 58.8,55.27 75.69,55.27 77.22,56.79 J15.24
GPIO-34: length 113.8
  TOP w0.254: J15.25 75.83,60.19 75.83,54.06 v1(77.67,52.22) 80.66,49.23 JP10.1 ; v1(60.97,52.22) 54.43,52.22 J5.1
  LAYER3 w0.254: v1(60.97,52.22) v1(77.67,52.22) ; J5.1 47.38,41.19 48.66,41.19 J1.46
GPIO-48: length 45
  TOP w0.254: v1(73.55,41.4) 81.71,41.4 J5.16
  LAYER3 w0.254: J1.30 74.17,36 74.17,40.79 v1(73.55,41.4)
  BOTTOM w0.254: J5.16 83.49,59.64 83.17,59.96 73.52,59.96 J15.27
GPIO-49: length 38.6
  LAYER3 w0.254: J1.80 74.3,34.38 73.03,35.65 73.03,37.49 72.17,38.34 72.17,47.72 v1(74.7,50.25)
  BOTTOM w0.254: J15.26 74.7,58.78 v1(74.7,50.25) ; J4.13 75.77,24.79 74.3,26.26 J1.80
GPIO-58: length 69.3
  LAYER3 w0.254: J15.29 70.87,60.07 106.27,60.07 106.81,59.54 106.81,47.09 106.35,46.63 J5.25
  BOTTOM w0.254: J5.25 102.69,39.52 98.26,39.52 J1.18
GPIO-59: length 71.5
  TOP w0.254: J15.28 72.14,41.3 72.75,40.69 73.74,40.69 73.74,40.69 84.05,40.69 84.23,40.87 86.72,40.87 87.78,39.8 87.78,25.04 88.51,24.32 97.04,24.32 J4.22
  BOTTOM w0.254: J4.22 94.62,26.75 J1.68
GPIO-60: length 70.9
  BOTTOM w0.254: J15.31 68.21,62.5 96.38,62.5 96.38,55.54 102.42,55.54 102.42,43.18 ; 102.42,43.18 102.42,41.48 101.75,40.81 97.02,40.81 J1.20 ; 102.42,43.18 J5.24
GPIO-61: length 58.4
  TOP w0.254: J1.70 91.28,32.87 90.23,32.87 88.38,34.72 88.38,40.27 87.25,41.4 85.52,41.4 84.87,42.04 84.87,46.09 83.87,47.09 74.03,47.09 73.03,48.09 73.03,57.45 73.38,57.81 73.38,59.7 73.13,59.96 70.75,59.96 J15.30
  BOTTOM w0.254: J1.70 92.07,26.75 J4.21
GPIO-62: length 72.9
  TOP w0.254: J1.22 90.45,36.78 90.45,39.09 92.94,41.58 99.67,41.58 J5.23 ; v1(101.27,54.84) 101.27,55.78 101.47,55.98 101.47,58.31 101.46,58.32 101.46,62.05 100.77,62.74 65.91,62.74 J15.33
  BOTTOM w0.254: v1(101.27,54.84) J5.23
GPIO-63: length 59.4
  TOP w0.254: v1(67.06,38.02) 83.88,38.02 85.25,36.65 v1(85.25,32.07)
  BOTTOM w0.254: v1(85.25,32.07) J1.72 89.54,26.75 J4.20 ; J15.32 v1(67.06,38.02)
GPIO-84: length 88.5
  LAYER3 w0.254: JP9.1 132.32,19.11 132.32,42.03 82.1,42.03 J5.15
  BOTTOM w0.254: J5.15 78.76,40.99 77.7,40.99 73.24,36.53 73.24,34.19 J1.31
GPIO-85: length 71.5
  TOP w0.254: J4.12 73.23,18.44 74.55,17.12 78.87,17.12 v1(80.01,15.98)
  BOTTOM w0.254: J1.81 73.03,22.94 J4.12 ; JP8.1 v1(80.01,15.98)
GPIO-86: length 90.9
  LAYER3 w0.254: JP7.1 129.78,15.38 129.78,41.02 129.53,41.27 104.3,41.27 104.27,41.3 80.29,41.3 J5.14
  BOTTOM w0.254: J1.32 77.63,41.74 77.63,42.4 J5.14
GPIO-87: length 132.2
  BOTTOM w0.254: J5.5 59.06,39.67 J1.42 59.06,33.56 60.11,32.51 60.11,31.63 58.84,30.36 58.84,27.49 57.11,25.77 52.94,25.77 51.75,24.58 51.75,2.93 52.76,1.93 105.38,1.93 114.1,10.64 JP6.1
RX-ISO: length 22.6
  TOP w0.254: J3.4 141.26,36.5 140.63,35.87 J1.2
RX_SLAVE: length 34.5
  TOP w0.254: JP4.2 47.98,20.45 49.02,21.49 49.02,24.69 49.91,25.58 55.78,25.58 58.98,28.78 58.98,30.56 57.79,31.75 J1.43
  BOTTOM w0.254: J5.4 53.79,42.4 53.79,41.43 57.79,37.44 J1.43
TCK: length 80.2
  TOP w0.254: U1.24 33.86,1.97 34.08,1.75 36.22,1.75 v1(36.93,2.46) ; J1.48 50.42,35.87 47.78,33.22 47.78,31.98 46.53,30.73 42.74,30.73 38.47,35 v1(37.82,35)
  LAYER3 w0.254: J2.11 21.46,26.92 21.46,12.95 22.71,11.71 31.42,11.71 36.93,6.2 v1(36.93,2.46)
  BOTTOM w0.254: v1(37.82,35) 36.75,33.93 30.35,33.93 26.26,29.84 24.23,29.84 J2.9 J2.11
TDI: length 74.3
  TOP w0.254: v1(38.33,2.14) 37,0.82 33.2,0.82 33.05,0.96 33.05,1.01 32.96,1.11 U1.23
  LAYER3 w0.254: J2.3 24.36,39.98 27.69,39.98 28.04,39.62 28.04,33.9 33.7,28.24 v1(35.15,28.24)
  BOTTOM w0.254: v1(38.33,2.14) 38.33,5.69 34.26,9.75 34.26,27.36 v1(35.15,28.24) 35.69,28.78 51.31,28.78 J1.97
TDO: length 83
  TOP w0.254: v1(35.15,35) 36.01,35 37.43,33.58 38,33.58 41.55,30.02 48.34,30.02 50.39,32.07 J1.98 ; J2.7 19.77,36.85 19.61,36.85 v1(19.15,37.31) ; v1(32.66,3.71) 32.46,3.5 U1.22
  BOTTOM w0.254: v1(19.15,37.31) 20.93,35.53 20.93,24.51 24.13,21.31 29.46,21.31 30.35,20.42 30.35,5.2 31.85,3.71 v1(32.66,3.71) ; v1(35.15,35) 29.29,35 26.62,32.33 24.28,32.33 J2.7
TMS: length 82.5
  TOP w0.254: U1.21 31.96,3.39 31.31,4.03 31.31,4.31 v1(31.78,4.78)
  BOTTOM w0.254: J1.49 50.17,37.24 48.49,38.91 31.14,38.91 30.89,39.17 30.89,40.51 28.22,43.18 25.02,43.18 J2.1 21.82,39.98 21.82,24.69 24.31,22.2 30.71,22.2 31.06,21.84 31.06,5.49 v1(31.78,4.78)
TRSTN: length 63
  TOP w0.254: U1.20 31.46,3.12 30.36,4.23 30.36,4.6 v1(31.78,6.02)
  LAYER3 w0.254: J2.2 26.68,41.2 26.71,41.22 28.22,41.22 29.11,40.34 29.11,34.11 33.2,30.02 v1(34.09,30.02)
  BOTTOM w0.254: J1.99 49.16,30.17 49.01,30.02 v1(34.09,30.02) 31.86,27.8 31.86,23.65 31.78,23.56 v1(31.78,6.02)
TX-ISO: length 23.7
  BOTTOM w0.254: J3.1 134.09,28.88 132.05,30.91 122.99,30.91 121.83,32.07 J1.52
TX_SLAVE: length 176.1
  TOP w0.254: U1.39 32.46,10.97 32.55,11.07 32.55,11.08 32.7,11.22 32.71,11.22 33.02,11.53 34.5,11.53 35.74,10.29 v1(36.4,10.29)
  BOTTOM w0.254: JP11.1 127.61,52.07 115.89,63.79 44.97,63.79 44.23,63.05 44.23,40.21 45.1,39.34 50.01,39.34 52.58,36.78 52.58,35.71 53.97,34.32 53.97,33.75 54.81,32.92 55.68,32.92 55.99,33.22 57.04,33.22 57.79,32.48 J1.93 57.79,28.3 56.49,27 52.04,27 50.37,25.32 J4.3 50.37,19.28 41.38,10.29 v1(36.4,10.29)
USB_D+: length 33.9
  TOP w0.254: v1(15.06,9.75) 15.52,9.29 15.52,7.58 15.75,7.36 R4.1 ; R3.2 15.5,19 16.48,19 17.2,18.29 v1(17.2,12.6) ; U1.7 27.97,5.77 v1(28.49,6.29)
  BOTTOM w0.254: v1(28.49,6.29) 28.02,6.75 15.58,6.75 15.06,7.26 v1(15.06,9.75) 17.2,11.89 v1(17.2,12.6)
USB_D-: length 26.4
  TOP w0.254: R2.2 v1(15.15,15) ; v1(29.64,6.2) 28.71,5.27 U1.8
  BOTTOM w0.254: v1(15.15,15) 15.77,14.38 17.67,14.38 18.44,13.6 18.44,7.87 18.69,7.62 28.22,7.62 v1(29.64,6.2)
N12195: length 55.8
  TOP w0.635: J9.1 6.53,40.16 8.84,42.47 12.93,42.47 14.35,43.89 14.35,48.49 14.3,48.54 J8.1 14.3,57.4 ; 14.3,57.4 14.3,60.27 C1.1 ; 14.3,57.4 16.15,57.4 PM1.2
N12272: length 78.1
  TOP w0.635: PM1.1 16.15,63.8 12.25,63.8 C1.2 8.5,60.06 J8.2 8.5,48.54 8.48,48.53 8.48,45.85 4.57,41.94 4.57,16.64 J9.2
  BOTTOM w0.635: JP2.2 30.15,55.83 26.97,59 20.96,59 PM1.1
N18531: length 4.8
  TOP w0.254: C8.1 27.15,21.31 25.99,20.14 U2.5
N22439: length 27.9
  TOP w0.254: R2.1 12.76,16.51 12.22,17.06 12.22,20.88 12.47,21.13 14.27,21.13 15.06,21.92 15.06,24.33 15.6,24.87 17.14,24.87 17.77,24.24 TVS1.8 18.67,24.7 18.62,24.75 18.62,33.76 18.08,34.3 J10.2
N22457: length 29.8
  TOP w0.254: J10.3 14.57,35.71 19.33,35.71 19.86,35.18 19.86,23.23 19.58,22.94 TVS1.6 17.58,22.94 14.71,20.07 13,20.07 12.75,19.81 12.75,18.9 13,18.64 R3.1
N23366: length 10.9
  TOP w0.254: U1.5 24.83,6.77 24.15,7.44 18.97,7.44 17.47,8.95 R4.2
N23404: length 6.8
  TOP w0.254: U1.44 29.96,11.61 28.85,12.71 U5.1 28.85,15.45 R5.2
N23422: length 7
  TOP w0.254: U1.43 30.46,11.32 31.85,12.71 U5.3 31.85,15.45 R5.1
N24717: length 12.6
  TOP w0.254: U1.6 24.71,6.27 23.97,7.01 19.08,7.01 17.2,5.13 C9.2
N25180: length 2.8
  TOP w0.254: D1.2 38.09,15.65 37.67,16.07 R6.2
N25279: length 27.9
  TOP w0.254: L1.2 R1.1 21.46,9.22 22.17,8.51 24.31,8.51 25.05,7.77 U1.3 29.81,7.77 30.96,8.92 U1.42 30.96,11.07 31.6,11.71 31.88,11.71 34.9,14.73 36.02,14.73 38.11,12.64 C11.1 C12.1
N25286: length 9.3
  TOP w0.254: R1.2 23.04,12.5 C10.2 23.93,12.31 24.51,11.72 28.64,11.72 28.96,11.4 U1.46
N28281: length 16.4
  LAYER3 w0.254: JP3.2 30.71,29.84 27.24,33.31 27.24,36.69 26.62,37.31 24.23,37.31 J2.5
N29672: length 24
  TOP w0.254: U4.1 8.27,2.86 v1(7.77,3.35) ; v1(25.37,2.29) 25.37,3.4 25.75,3.77 U1.11
  LAYER3 w0.254: v1(25.37,2.29) 25.37,1.4 24.83,0.85 9.39,0.85 7.92,2.32 7.92,2.4 7.77,2.54 v1(7.77,3.35)
N29684: length 29.6
  TOP w0.254: v1(8.13,4.6) 9.3,4.6 9.55,4.34 9.55,2.11 10.3,1.36 U4.5 ; U1.12 v1(26.66,2.11)
  BOTTOM w0.254: v1(8.13,4.6) 9.3,4.6 9.55,4.34 9.55,1.81 10.52,0.85 25.4,0.85 v1(26.66,2.11)
N29790: length 18.6
  TOP w0.254: v1(36.04,11.71) 35.24,12.51 33.28,12.51 31.96,11.18 U1.40
  BOTTOM w0.254: v1(36.04,11.71) 37.97,11.71 JP4.1
N34054: length 4.5
  TOP w0.254: U6.1 21.22,4.32 R7.1 20.04,5.12 20.94,6.02 R8.1
N34072: length 16
  TOP w0.254: U1.2 25.26,8.27 v1(24.13,9.4) ; U6.3 21,2.76 20.98,2.74 R7.2 v1(20.04,1.67)
  LAYER3 w0.254: v1(24.13,9.4) 23.42,9.4 22.71,8.69 22.71,3.35 21.02,1.67 v1(20.04,1.67)
N34220: length 13.2
  TOP w0.254: v1(25.2,9.93) 25.2,9.48 25.91,8.77 U1.1 ; v1(24.13,1.57) 24.13,2.49 U6.4
  LAYER3 w0.254: v1(25.2,9.93) 25.2,9.28 24.61,8.69 24.31,8.69 23.24,7.62 23.24,2.46 v1(24.13,1.57)
N34232: length 9.5
  TOP w0.254: U6.5 24.49,3.71 v1(25.02,4.24) ; U1.48 27.56,10.46 v1(27.15,10.46)
  LAYER3 w0.254: v1(25.02,4.24) 25.02,8.33 v1(27.15,10.46)
N41056: length 13
  TOP w0.254: R9.2 15.15,2.23 ; 15.15,2.23 15.15,3.18 15.13,3.2 C17.1 ; 15.15,2.23 14.2,3.17 12.81,3.17 11.86,4.12 v1(11.86,4.78) ; v1(10.08,5.13) 10.08,2.64 10.87,1.86 U4.6
  LAYER3 w0.254: v1(11.86,4.78) 11.21,4.78 10.85,5.13 v1(10.08,5.13)
N43288: length 5.9
  TOP w0.254: R11.1 10.97,8.6 10.97,9.17 10.72,9.42 8.28,9.42 7.42,10.29 JP5.1
N46408: length 2.9
  TOP w0.254: JP10.2 R16.1
N46412: length 2.9
  TOP w0.254: JP11.2 R17.1
N46416: length 2.9
  TOP w0.254: JP12.2 R18.1
N46420: length 3.4
  TOP w0.254: JP6.2 R12.1
N46424: length 3.4
  TOP w0.254: JP7.2 R13.1
N46428: length 3.4
  TOP w0.254: JP8.2 R14.1
N46432: length 3.4
  TOP w0.254: JP9.2 R15.1

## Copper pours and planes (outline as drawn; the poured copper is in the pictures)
GND_SIGNAL on LAYER2: 0.66,0.69 0.66,65.4 144.14,65.4 144.14,0.69

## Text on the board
Ref Des/Silkscreen Top: 9V-36V | RST | Serial | IDC_A | IDC_B | Small_UCB | V2.1C | Chris Farnell | 25Aug2016 | + | - | USB | 5V | EXT | Gnd_A | Gnd_D | 3V3 | GND | GPIO | 33 | 34 | 31 | 32 | 29 | 30 | 23 | 28 | 21 | 87 | 19 | 22 | 17 | 20 | 18 | 27 | 16 | 25 | 26 | 14 | 13 | 24 | 15 | 85 | 12 | 49 | 11 | 86 | 09 | 84 | 07 | 48 | 05 | 10 | 03 | 08 | 06 | 01 | 04 | 63 | 61 | 02 | 59 | 00 | 62 | 60 | 58 | ADC | A7 | B7 | A6 | B6 | A5 | B5 | A4 | B4 | 280xx | 2833x | A3 | Boot | B3 | A2 | B2 | A1 | B1 | A0 | B0 | RS232 | V33 | TX | RX
